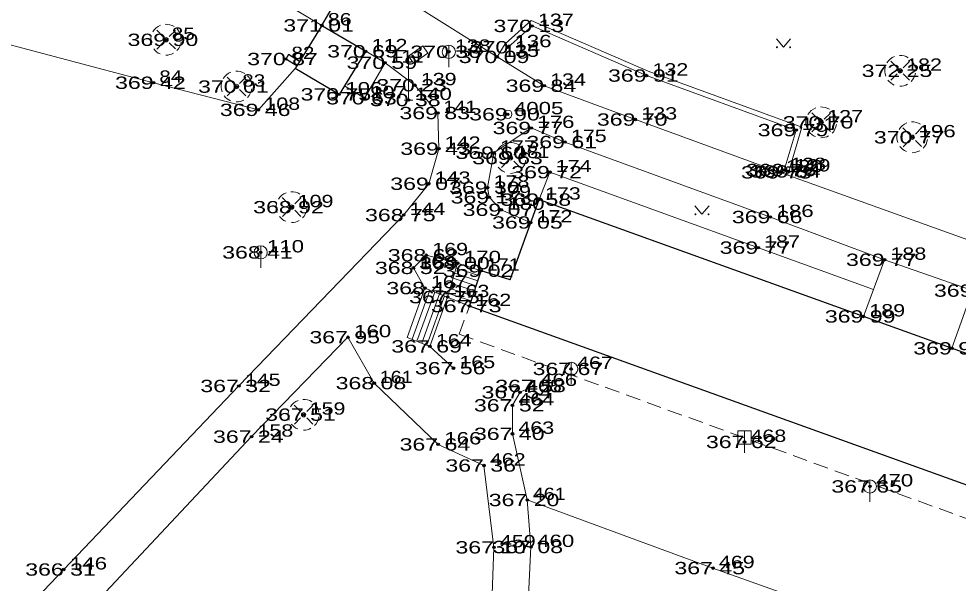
# Model space of a CAD drawing. Extents: x -789669 to -789458, y -977587 to -977420.
# Drawn here: x -789622.4 to -789569.1, y -977494.5 to -977462.4 of the extents above; entities that cross this region are included whole.
import ezdxf
from ezdxf.enums import TextEntityAlignment as Align

# ---------------------------------------------------------------- set-up
doc = ezdxf.new("R2010")
doc.units = 0
doc.header["$LTSCALE"] = 0.28
doc.header["$PDMODE"] = 32
doc.header["$PDSIZE"] = 0.14
doc.linetypes.add('MEDIUM_DASHED', pattern=[4.5, 3, -1.5])
for name, color, linetype, lineweight in [('1', 7, 'Continuous', 13), ('25', 7, 'Continuous', 13), ('3', 7, 'Continuous', 13), ('33', 7, 'Continuous', 13), ('4', 7, 'Continuous', 13), ('50', 7, 'Continuous', 13), ('9', 7, 'Continuous', 25)]:
    doc.layers.add(name, color=color, linetype=linetype, lineweight=lineweight)
for name, color, linetype in [('57', 7, 'Continuous'), ('58', 7, 'Continuous'), ('59', 7, 'Continuous')]:
    doc.layers.add(name, color=color, linetype=linetype)

msp = doc.modelspace()

# ---------------------------------------------------------------- linework, layer by layer
at = {"layer": '1'}
for p, q in [((-789595.27, -977464.56), (-789594.824, -977463.816)), ((-789602.74, -977464.24), (-789601.64, -977464.89)), ((-789601.64, -977464.89), (-789602.8, -977466.91)), ((-789603.949, -977466.202), (-789602.8, -977466.91)), ((-789578.805, -977471.28), (-789578.73, -977471.07)), ((-789597.52, -977476.28), (-789598.09, -977478.21)), ((-789597.52, -977476.28), (-789596.18, -977476.71)), ((-789573.29, -977476.09), (-789574.49, -977479.31)), ((-789597.69, -977476.855), (-789596.37, -977477.279)), ((-789597.605, -977476.568), (-789596.275, -977476.995)), ((-789597.86, -977477.432), (-789596.56, -977477.849)), ((-789597.775, -977477.143), (-789596.465, -977477.564)), ((-789600.39, -977480.5), (-789599.38, -977477.7)), ((-789600.111, -977480.61), (-789599.101, -977477.81)), ((-789599.832, -977480.721), (-789598.822, -977477.921)), ((-789597.945, -977477.719), (-789596.654, -977478.133)), ((-789568.3, -977477.84), (-789569.47, -977481.12)), ((-789599.552, -977480.831), (-789598.542, -977478.031)), ((-789599.273, -977480.941), (-789598.263, -977478.141)), ((-789598.03, -977478.007), (-789596.749, -977478.418)), ((-789599.1, -977481.01), (-789600.39, -977480.5))]:
    msp.add_line(p, q, dxfattribs=at)
for points in [[(-789605.23, -977462.77), (-789609.01, -977460.5), (-789610.31, -977459.07), (-789610.84, -977457.94), (-789611.05, -977457.83), (-789612.47, -977456.96), (-789628.38, -977447.2), (-789642.41, -977438.73)], [(-789600.83, -977460.98), (-789599.99, -977461.6), (-789595.27, -977464.56), (-789592.61, -977466.2), (-789587.43, -977468.12), (-789579.25, -977471.12)], [(-789601.64, -977464.89), (-789599.95, -977466.17), (-789598.64, -977467.75), (-789598.59, -977469.78), (-789599.16, -977471.77), (-789600.59, -977473.55), (-789609.94, -977483.26), (-789619.88, -977493.69), (-789629.88, -977504.18), (-789634.89, -977509.42), (-789637.37, -977512.43)], [(-789591.43, -977469.4), (-789593.35, -977468.6), (-789595.46, -977470.01), (-789595.82, -977471.99), (-789595.73, -977472.54), (-789595.05, -977473.25), (-789593.38, -977473.97)], [(-789591.43, -977469.4), (-789579.77, -977473.66), (-789573.29, -977476.09), (-789568.3, -977477.84), (-789563.66, -977479.48), (-789554.46, -977482.75), (-789542.34, -977487.22), (-789543.54, -977490.46)], [(-789592.9, -977472.67), (-789592.29, -977471.11), (-789573.917, -977477.772)], [(-789528.28, -977489.67), (-789537.88, -977485.96), (-789544.73, -977483.69), (-789553.55, -977480.4), (-789562.72, -977477.06), (-789579.25, -977471.12)], [(-789596.18, -977476.71), (-789597.52, -977476.28), (-789599.3, -977475.83), (-789600.03, -977476.55), (-789599.38, -977477.7), (-789598.09, -977478.21), (-789596.85, -977478.72)], [(-789597.76, -977482.25), (-789599.1, -977481.01), (-789598.09, -977478.21)], [(-789624.85, -977503.61), (-789625.01, -977502.71), (-789618.92, -977496.49), (-789609.22, -977486.14), (-789603.75, -977480.49), (-789602.26, -977483.1), (-789598.63, -977486.58)], [(-789593.53, -977495.98), (-789593.36, -977492.41), (-789593.57, -977489.74), (-789594.41, -977485.98), (-789594.41, -977484.36), (-789594.41, -977484.36), (-789593.98, -977483.62), (-789593.2, -977483.26)], [(-789598.63, -977486.58), (-789596.03, -977487.78), (-789595.46, -977492.43), (-789595.58, -977495.6), (-789596.49, -977499.86), (-789598.03, -977504.82)], [(-789555.4, -977503.56), (-789567.6, -977499.13), (-789583.03, -977493.61), (-789593.57, -977489.74)]]:
    msp.add_lwpolyline(points, dxfattribs=at)
at = {"layer": '25'}
for p, q in [((-789598.022, -977465.144), (-789598.022, -977463.895)), ((-789608.702, -977476.544), (-789608.702, -977475.295)), ((-789591.082, -977483.164), (-789591.082, -977481.915)), ((-789574.122, -977489.844), (-789574.122, -977488.595))]:
    msp.add_line(p, q, dxfattribs=at)
msp.add_lwpolyline([(-789581.24, -977487.065), (-789581.24, -977485.815), (-789580.865, -977485.815), (-789580.865, -977486.565), (-789581.615, -977486.565), (-789581.615, -977485.815), (-789581.24, -977485.815)], dxfattribs=at)
for centre in [(-789598.02, -977464.27), (-789608.7, -977475.67), (-789591.08, -977482.29), (-789574.12, -977488.97)]:
    msp.add_circle(centre, 0.375, dxfattribs=at)
at = {"layer": '3', "lineweight": 25}
msp.add_line((-789605.23, -977462.77), (-789603.31, -977459.5), dxfattribs=at)
at = {"layer": '3'}
for p, q in [((-789594.65, -977464.01), (-789594.824, -977463.816)), ((-789578.98, -977470.99), (-789578.73, -977471.07))]:
    msp.add_line(p, q, dxfattribs=at)
for points in [[(-789666.71, -977502.39), (-789654.87, -977463.01), (-789641.19, -977459.01), (-789614.78, -977466.03), (-789608.83, -977467.57), (-789606.74, -977465.22)], [(-789578.73, -977471.07), (-789577.981, -977468.56), (-789586.704, -977465.378), (-789593.349, -977462.495), (-789594.824, -977463.816)], [(-789578.98, -977470.99), (-789578.3, -977468.72), (-789586.8, -977465.62), (-789593.3, -977462.8), (-789594.65, -977464.01)]]:
    msp.add_lwpolyline(points, dxfattribs=at)
at = {"layer": '33'}
for p, q in [((-789600.31, -977464.51), (-789600.31, -977467.01)), ((-789600.56, -977467.01), (-789600.06, -977467.01))]:
    msp.add_line(p, q, dxfattribs=at)
msp.add_lwpolyline([(-789600.31, -977464.51), (-789599.49, -977463.937), (-789599.204, -977464.347), (-789600.024, -977464.92)], close=True, dxfattribs=at)
at = {"layer": '4'}
for p, q in [((-789614.604, -977463.046), (-789614.247, -977463.402)), ((-789614.07, -977463.59), (-789614.07, -977463.578)), ((-789613.544, -977463.054), (-789613.897, -977463.407)), ((-789614.6, -977464.117), (-789614.248, -977463.766)), ((-789613.896, -977463.761), (-789613.544, -977464.111)), ((-789572.934, -977464.812), (-789572.577, -977465.168)), ((-789571.874, -977464.82), (-789572.227, -977465.173)), ((-789610.604, -977465.706), (-789610.247, -977466.062)), ((-789609.544, -977465.714), (-789609.897, -977466.067)), ((-789572.93, -977465.883), (-789572.578, -977465.532)), ((-789572.4, -977465.356), (-789572.4, -977465.344)), ((-789572.226, -977465.527), (-789571.874, -977465.877)), ((-789610.07, -977466.25), (-789610.07, -977466.238)), ((-789610.6, -977466.777), (-789610.248, -977466.426)), ((-789609.896, -977466.421), (-789609.544, -977466.771)), ((-789577.414, -977467.742), (-789577.057, -977468.098)), ((-789576.354, -977467.75), (-789576.707, -977468.103)), ((-789576.88, -977468.286), (-789576.88, -977468.274)), ((-789577.41, -977468.813), (-789577.058, -977468.462)), ((-789576.706, -977468.457), (-789576.354, -977468.807)), ((-789572.244, -977468.592), (-789571.887, -977468.948)), ((-789571.184, -977468.6), (-789571.537, -977468.953)), ((-789572.24, -977469.663), (-789571.888, -977469.312)), ((-789571.71, -977469.136), (-789571.71, -977469.124)), ((-789571.536, -977469.307), (-789571.184, -977469.657)), ((-789595.044, -977469.766), (-789594.687, -977470.122)), ((-789593.984, -977469.774), (-789594.337, -977470.127)), ((-789595.04, -977470.837), (-789594.688, -977470.486)), ((-789594.51, -977470.31), (-789594.51, -977470.298)), ((-789594.336, -977470.481), (-789593.984, -977470.831)), ((-789607.474, -977472.556), (-789607.117, -977472.912)), ((-789606.414, -977472.564), (-789606.767, -977472.917)), ((-789606.94, -977473.1), (-789606.94, -977473.088)), ((-789607.47, -977473.627), (-789607.118, -977473.276)), ((-789606.766, -977473.271), (-789606.414, -977473.621)), ((-789606.794, -977484.358), (-789606.437, -977484.714)), ((-789605.734, -977484.366), (-789606.087, -977484.719)), ((-789606.26, -977484.902), (-789606.26, -977484.89)), ((-789606.79, -977485.429), (-789606.438, -977485.078)), ((-789606.086, -977485.073), (-789605.734, -977485.423))]:
    msp.add_line(p, q, dxfattribs=at)
for points in [[(-789579.423, -977463.534), (-789579.021, -977464.013), (-789578.619, -977463.534)], [(-789579.395, -977463.99), (-789579.381, -977463.998), (-789579.376, -977464.013), (-789579.382, -977464.026), (-789579.395, -977464.034), (-789579.411, -977464.026), (-789579.417, -977464.013), (-789579.413, -977463.999), (-789579.402, -977463.993), (-789579.387, -977463.999), (-789579.382, -977464.013), (-789579.385, -977464.023), (-789579.395, -977464.028), (-789579.406, -977464.023), (-789579.412, -977464.012), (-789579.407, -977464.002), (-789579.402, -977463.999), (-789579.391, -977464.003), (-789579.386, -977464.013), (-789579.392, -977464.02), (-789579.4, -977464.018), (-789579.405, -977464.01), (-789579.4, -977464.005), (-789579.392, -977464.009), (-789579.395, -977464.013)], [(-789578.645, -977463.991), (-789578.631, -977463.999), (-789578.626, -977464.014), (-789578.632, -977464.027), (-789578.645, -977464.035), (-789578.661, -977464.027), (-789578.667, -977464.014), (-789578.663, -977464), (-789578.652, -977463.994), (-789578.637, -977464), (-789578.632, -977464.014), (-789578.635, -977464.024), (-789578.645, -977464.029), (-789578.656, -977464.024), (-789578.662, -977464.013), (-789578.657, -977464.003), (-789578.652, -977464), (-789578.641, -977464.004), (-789578.636, -977464.014), (-789578.642, -977464.021), (-789578.65, -977464.019), (-789578.655, -977464.011), (-789578.65, -977464.006), (-789578.642, -977464.01), (-789578.645, -977464.014)], [(-789584.053, -977473.027), (-789583.651, -977473.506), (-789583.249, -977473.027)], [(-789584.025, -977473.483), (-789584.011, -977473.491), (-789584.006, -977473.506), (-789584.012, -977473.519), (-789584.025, -977473.527), (-789584.041, -977473.519), (-789584.047, -977473.506), (-789584.043, -977473.492), (-789584.032, -977473.486), (-789584.017, -977473.492), (-789584.012, -977473.506), (-789584.015, -977473.516), (-789584.025, -977473.521), (-789584.036, -977473.516), (-789584.042, -977473.505), (-789584.037, -977473.495), (-789584.032, -977473.492), (-789584.021, -977473.496), (-789584.016, -977473.506), (-789584.022, -977473.513), (-789584.03, -977473.511), (-789584.035, -977473.503), (-789584.03, -977473.498), (-789584.022, -977473.502), (-789584.025, -977473.506)], [(-789583.275, -977473.484), (-789583.261, -977473.492), (-789583.256, -977473.507), (-789583.262, -977473.52), (-789583.275, -977473.528), (-789583.291, -977473.52), (-789583.297, -977473.507), (-789583.293, -977473.493), (-789583.282, -977473.487), (-789583.267, -977473.493), (-789583.262, -977473.507), (-789583.265, -977473.517), (-789583.275, -977473.522), (-789583.286, -977473.517), (-789583.292, -977473.506), (-789583.287, -977473.496), (-789583.282, -977473.493), (-789583.271, -977473.497), (-789583.266, -977473.507), (-789583.272, -977473.514), (-789583.28, -977473.512), (-789583.285, -977473.504), (-789583.28, -977473.499), (-789583.272, -977473.503), (-789583.275, -977473.507)]]:
    msp.add_lwpolyline(points, dxfattribs=at)
for centre, radius in [((-789614.0739, -977463.5834), 0.125), ((-789579.396, -977464.013), 0.025), ((-789578.646, -977464.013), 0.025), ((-789572.4039, -977465.3494), 0.125), ((-789610.0739, -977466.2434), 0.125), ((-789576.8839, -977468.2794), 0.125), ((-789571.7139, -977469.1294), 0.125), ((-789594.5139, -977470.3034), 0.125), ((-789606.9439, -977473.0934), 0.125), ((-789584.0262, -977473.5057), 0.025), ((-789583.2762, -977473.5057), 0.025), ((-789606.2639, -977484.8954), 0.125)]:
    msp.add_circle(centre, radius, dxfattribs=at)
for centre, start, end in [((-789614.0739, -977463.5834), 111.04924, 149.34666), ((-789614.0739, -977463.5834), 57.94289, 92.85253), ((-789614.0739, -977463.5834), 9.68453, 44.47714), ((-789614.0739, -977463.5834), 166.76695, 200.11735), ((-789614.0739, -977463.5834), 217.06959, 247.69959), ((-789614.0739, -977463.5834), 315.09105, 351.67435), ((-789614.0739, -977463.5834), 269.18965, 298.56841), ((-789572.4039, -977465.3494), 111.04924, 149.34666), ((-789572.4039, -977465.3494), 57.94289, 92.85253), ((-789572.4039, -977465.3494), 166.76695, 200.11735), ((-789572.4039, -977465.3494), 9.68453, 44.47714), ((-789610.0739, -977466.2434), 111.04924, 149.34666), ((-789610.0739, -977466.2434), 57.94289, 92.85253), ((-789610.0739, -977466.2434), 9.68453, 44.47714), ((-789572.4039, -977465.3494), 315.09105, 351.67435), ((-789610.0739, -977466.2434), 166.76695, 200.11735), ((-789572.4039, -977465.3494), 217.06959, 247.69959), ((-789572.4039, -977465.3494), 269.18965, 298.56841), ((-789610.0739, -977466.2434), 217.06959, 247.69959), ((-789610.0739, -977466.2434), 315.09105, 351.67435), ((-789610.0739, -977466.2434), 269.18965, 298.56841), ((-789576.8839, -977468.2794), 111.04924, 149.34666), ((-789576.8839, -977468.2794), 57.94289, 92.85253), ((-789576.8839, -977468.2794), 9.68453, 44.47714), ((-789576.8839, -977468.2794), 166.76695, 200.11735), ((-789571.7139, -977469.1294), 111.04924, 149.34666), ((-789571.7139, -977469.1294), 57.94289, 92.85253), ((-789576.8839, -977468.2794), 217.06959, 247.69959), ((-789576.8839, -977468.2794), 315.09105, 351.67435), ((-789571.7139, -977469.1294), 9.68453, 44.47714), ((-789594.5139, -977470.3034), 57.94289, 92.85253), ((-789576.8839, -977468.2794), 269.18965, 298.56841), ((-789571.7139, -977469.1294), 166.76695, 200.11735), ((-789571.7139, -977469.1294), 315.09105, 351.67435), ((-789594.5139, -977470.3034), 111.04924, 149.34666), ((-789594.5139, -977470.3034), 9.68453, 44.47714), ((-789571.7139, -977469.1294), 217.06959, 247.69959), ((-789571.7139, -977469.1294), 269.18965, 298.56841), ((-789594.5139, -977470.3034), 166.76695, 200.11735), ((-789594.5139, -977470.3034), 315.09105, 351.67435), ((-789594.5139, -977470.3034), 217.06959, 247.69959), ((-789594.5139, -977470.3034), 269.18965, 298.56841), ((-789606.9439, -977473.0934), 111.04924, 149.34666), ((-789606.9439, -977473.0934), 57.94289, 92.85253), ((-789606.9439, -977473.0934), 9.68453, 44.47714), ((-789606.9439, -977473.0934), 166.76695, 200.11735), ((-789606.9439, -977473.0934), 217.06959, 247.69959), ((-789606.9439, -977473.0934), 315.09105, 351.67435), ((-789606.9439, -977473.0934), 269.18965, 298.56841), ((-789606.2639, -977484.8954), 111.04924, 149.34666), ((-789606.2639, -977484.8954), 57.94289, 92.85253), ((-789606.2639, -977484.8954), 9.68453, 44.47714), ((-789606.2639, -977484.8954), 166.76695, 200.11735), ((-789606.2639, -977484.8954), 217.06959, 247.69959), ((-789606.2639, -977484.8954), 315.09105, 351.67435), ((-789606.2639, -977484.8954), 269.18965, 298.56841)]:
    msp.add_arc(centre, 0.875, start, end, dxfattribs=at)
at = {"layer": '50'}
msp.add_line((-789594.688, -977467.82), (-789594.672, -977467.82), dxfattribs=at)
msp.add_circle((-789594.6798, -977467.8205), 0.24, dxfattribs=at)
at = {"layer": '57'}
for p in [(-789605.23, -977462.77), (-789593.3, -977462.8), (-789614.07, -977463.59), (-789594.65, -977464.01), (-789607.28, -977464.68), (-789602.74, -977464.24), (-789598.02, -977464.27), (-789595.27, -977464.56), (-789601.64, -977464.89), (-789586.8, -977465.62), (-789572.4, -977465.35), (-789614.78, -977466.03), (-789610.07, -977466.25), (-789599.95, -977466.17), (-789592.61, -977466.2), (-789604.25, -977466.69), (-789602.8, -977466.91), (-789600.31, -977467.01), (-789608.83, -977467.57), (-789598.64, -977467.75), (-789594.68, -977467.82), (-789587.43, -977468.12), (-789576.88, -977468.28), (-789593.35, -977468.6), (-789578.3, -977468.72), (-789591.43, -977469.4), (-789571.71, -977469.13), (-789598.59, -977469.78), (-789595.46, -977470.01), (-789594.51, -977470.31), (-789592.29, -977471.11), (-789579.25, -977471.12), (-789578.98, -977470.99), (-789578.73, -977471.07), (-789599.16, -977471.77), (-789595.82, -977471.99), (-789595.73, -977472.54), (-789592.9, -977472.67), (-789606.94, -977473.1), (-789595.05, -977473.25), (-789600.59, -977473.55), (-789579.77, -977473.66), (-789593.38, -977473.97), (-789608.7, -977475.67), (-789599.3, -977475.83), (-789580.46, -977475.4), (-789597.52, -977476.28), (-789573.29, -977476.09), (-789600.03, -977476.55), (-789596.18, -977476.71), (-789599.38, -977477.7), (-789598.09, -977478.21), (-789596.85, -977478.72), (-789574.49, -977479.31), (-789603.75, -977480.49), (-789599.1, -977481.01), (-789569.47, -977481.12), (-789597.76, -977482.25), (-789591.08, -977482.29), (-789609.94, -977483.26), (-789602.26, -977483.1), (-789593.2, -977483.26), (-789593.98, -977483.62), (-789594.41, -977484.36), (-789606.26, -977484.89), (-789594.41, -977485.98), (-789609.22, -977486.14), (-789598.63, -977486.58), (-789581.24, -977486.44), (-789596.03, -977487.78), (-789574.12, -977488.97), (-789593.57, -977489.74), (-789595.46, -977492.43), (-789593.36, -977492.41), (-789619.88, -977493.69), (-789583.03, -977493.61)]:
    msp.add_point(p, dxfattribs=at)
at = {"layer": '9'}
for p, q in [((-789605.23, -977462.77), (-789606.74, -977465.22)), ((-789607.123, -977464.425), (-789607.28, -977464.68)), ((-789606.49, -977464.815), (-789607.123, -977464.425)), ((-789606.647, -977465.07), (-789607.28, -977464.68)), ((-789604.25, -977466.69), (-789606.74, -977465.22)), ((-789594.546, -977477.235), (-789592.9, -977472.67)), ((-789592.9, -977472.67), (-789543.54, -977490.46)), ((-789596.85, -977478.72), (-789596.18, -977476.71)), ((-789594.546, -977477.235), (-789596.18, -977476.71)), ((-789546.04, -977497.05), (-789596.85, -977478.72))]:
    msp.add_line(p, q, dxfattribs=at)
at = {"layer": '9', "linetype": 'MEDIUM_DASHED', "lineweight": 13}
for q in [(-789596.85, -977478.72), (-789543.101, -977500.084)]:
    msp.add_line((-789597.427, -977480.319), q, dxfattribs=at)
at = {"layer": '9'}
msp.add_lwpolyline([(-789605.23, -977462.77), (-789602.74, -977464.24), (-789604.25, -977466.69)], dxfattribs=at)

# ---------------------------------------------------------------- texts
at = {"layer": '50', "width": 1.35}
msp.add_text(' 4005', height=0.7, dxfattribs=at).set_placement((-789594.68, -977467.82))
at = {"layer": '58'}
for s, width, p in [(' 86', 1.3, (-789605.23, -977462.77)), (' 137', 1.3, (-789593.3, -977462.8)), (' 85', 1.25, (-789614.07, -977463.59)), (' 112', 1.3, (-789602.74, -977464.24)), (' 138', 1.3, (-789598.02, -977464.27)), (' 136', 1.35, (-789594.65, -977464.01)), (' 82', 1.25, (-789607.28, -977464.68)), (' 135', 1.3, (-789595.27, -977464.56)), (' 111', 1.2, (-789601.64, -977464.89)), (' 182', 1.3, (-789572.4, -977465.35)), (' 132', 1.3, (-789586.8, -977465.62)), (' 84', 1.25, (-789614.78, -977466.03)), (' 83', 1.25, (-789610.07, -977466.25)), (' 139', 1.3, (-789599.95, -977466.17)), (' 134', 1.3, (-789592.61, -977466.2)), (' 106', 1.35, (-789604.25, -977466.69)), (' 107', 1.3, (-789602.8, -977466.91)), (' 140', 1.35, (-789600.31, -977467.01)), (' 108', 1.3, (-789608.83, -977467.57)), (' 141', 1.2, (-789598.64, -977467.75)), (' 4005', 1.35, (-789594.68, -977467.82)), (' 133', 1.3, (-789587.43, -977468.12)), (' 127', 1.3, (-789576.88, -977468.28)), (' 176', 1.35, (-789593.35, -977468.6)), (' 131', 1.2, (-789578.3, -977468.72)), (' 175', 1.3, (-789591.43, -977469.4)), (' 196', 1.35, (-789571.71, -977469.13)), (' 142', 1.3, (-789598.59, -977469.78)), (' 177', 1.3, (-789595.46, -977470.01)), (' 181', 1.2, (-789594.51, -977470.31)), (' 174', 1.3, (-789592.29, -977471.11)), (' 130', 1.35, (-789579.25, -977471.12)), (' 128', 1.3, (-789578.98, -977470.99)), (' 129', 1.3, (-789578.73, -977471.07)), (' 143', 1.3, (-789599.16, -977471.77)), (' 178', 1.3, (-789595.82, -977471.99)), (' 179', 1.3, (-789595.73, -977472.54)), (' 173', 1.3, (-789592.9, -977472.67)), (' 109', 1.3, (-789606.94, -977473.1)), (' 180', 1.35, (-789595.05, -977473.25)), (' 144', 1.3, (-789600.59, -977473.55)), (' 186', 1.35, (-789579.77, -977473.66)), (' 172', 1.3, (-789593.38, -977473.97)), (' 187', 1.3, (-789580.46, -977475.4)), (' 110', 1.35, (-789608.7, -977475.67)), (' 169', 1.3, (-789599.3, -977475.83)), (' 168', 1.3, (-789600.03, -977476.55)), (' 170', 1.35, (-789597.52, -977476.28)), (' 188', 1.3, (-789573.29, -977476.09)), (' 171', 1.2, (-789596.18, -977476.71)), (' 167', 1.3, (-789599.38, -977477.7)), (' 163', 1.3, (-789598.09, -977478.21)), (' 162', 1.3, (-789596.85, -977478.72)), (' 189', 1.3, (-789574.49, -977479.31)), (' 160', 1.35, (-789603.75, -977480.49)), (' 164', 1.3, (-789599.1, -977481.01)), (' 165', 1.3, (-789597.76, -977482.25)), (' 467', 1.3, (-789591.08, -977482.29)), (' 145', 1.3, (-789609.94, -977483.26)), (' 161', 1.2, (-789602.26, -977483.1)), (' 466', 1.35, (-789593.2, -977483.26)), (' 465', 1.3, (-789593.98, -977483.62)), (' 464', 1.3, (-789594.41, -977484.36)), (' 159', 1.3, (-789606.26, -977484.89)), (' 158', 1.3, (-789609.22, -977486.14)), (' 463', 1.3, (-789594.41, -977485.98)), (' 166', 1.35, (-789598.63, -977486.58)), (' 468', 1.3, (-789581.24, -977486.44)), (' 462', 1.3, (-789596.03, -977487.78)), (' 470', 1.35, (-789574.12, -977488.97)), (' 461', 1.2, (-789593.57, -977489.74)), (' 459', 1.3, (-789595.46, -977492.43)), (' 460', 1.35, (-789593.36, -977492.41)), (' 469', 1.3, (-789583.03, -977493.61)), (' 146', 1.35, (-789619.88, -977493.69))]:
    msp.add_text(s, height=0.7, dxfattribs=dict(at, width=width)).set_placement(p)
at = {"layer": '59', "width": 1.4}
for s, p in [('371 01 ', (-789605.23, -977463.12)), ('370 13 ', (-789593.3, -977463.15)), ('369 90 ', (-789614.07, -977463.94)), ('370 69 ', (-789602.74, -977464.59)), ('370 36 ', (-789598.02, -977464.62)), ('370 14 ', (-789594.65, -977464.36)), ('370 87 ', (-789607.28, -977465.03)), ('370 59 ', (-789601.64, -977465.24)), ('370 09 ', (-789595.27, -977464.91)), ('372 25 ', (-789572.4, -977465.7)), ('369 42 ', (-789614.78, -977466.38)), ('369 91 ', (-789586.8, -977465.97)), ('370 01 ', (-789610.07, -977466.6)), ('370 23 ', (-789599.95, -977466.52)), ('369 84 ', (-789592.61, -977466.55)), ('370 75 ', (-789604.25, -977467.04)), ('370 63 ', (-789602.8, -977467.26)), ('370 38 ', (-789600.31, -977467.36)), ('369 46 ', (-789608.83, -977467.92)), ('369 83 ', (-789598.64, -977468.1)), ('369 90 ', (-789594.68, -977468.17)), ('369 70 ', (-789587.43, -977468.47)), ('369 77 ', (-789593.35, -977468.95)), ('369 79 ', (-789578.3, -977469.07)), ('370 70 ', (-789576.88, -977468.63)), ('370 77 ', (-789571.71, -977469.48)), ('369 43 ', (-789598.59, -977470.13)), ('369 61 ', (-789591.43, -977469.75)), ('369 60 ', (-789595.46, -977470.36)), ('369 63 ', (-789594.51, -977470.66)), ('369 72 ', (-789592.29, -977471.46)), ('369 73 ', (-789579.25, -977471.47)), ('369 76 ', (-789578.98, -977471.34)), ('369 84 ', (-789578.73, -977471.42)), ('369 07 ', (-789599.16, -977472.12)), ('369 30 ', (-789595.82, -977472.34)), ('369 17 ', (-789595.73, -977472.89)), ('369 58 ', (-789592.9, -977473.02)), ('368 92 ', (-789606.94, -977473.45)), ('369 07 ', (-789595.05, -977473.6)), ('368 75 ', (-789600.59, -977473.9)), ('369 05 ', (-789593.38, -977474.32)), ('369 66 ', (-789579.77, -977474.01)), ('368 41 ', (-789608.7, -977476.02)), ('369 77 ', (-789580.46, -977475.75)), ('368 62 ', (-789599.3, -977476.18)), ('369 77 ', (-789573.29, -977476.44)), ('368 52 ', (-789600.03, -977476.9)), ('369 00 ', (-789597.52, -977476.63)), ('369 02 ', (-789596.18, -977477.06)), ('368 42 ', (-789599.38, -977478.05)), ('367 75 ', (-789598.09, -977478.56)), ('369 90 ', (-789568.3, -977478.19)), ('367 73 ', (-789596.85, -977479.07)), ('369 99 ', (-789574.49, -977479.66)), ('367 95 ', (-789603.75, -977480.84)), ('367 69 ', (-789599.1, -977481.36)), ('369 99 ', (-789569.47, -977481.47)), ('367 56 ', (-789597.76, -977482.6)), ('367 67 ', (-789591.08, -977482.64)), ('368 08 ', (-789602.26, -977483.45)), ('367 32 ', (-789609.94, -977483.61)), ('367 54 ', (-789593.98, -977483.97)), ('367 58 ', (-789593.2, -977483.61)), ('367 52 ', (-789594.41, -977484.71)), ('367 51 ', (-789606.26, -977485.24)), ('367 24 ', (-789609.22, -977486.49)), ('367 40 ', (-789594.41, -977486.33)), ('367 64 ', (-789598.63, -977486.93)), ('367 62 ', (-789581.24, -977486.79)), ('367 36 ', (-789596.03, -977488.13)), ('367 65 ', (-789574.12, -977489.32)), ('367 20 ', (-789593.57, -977490.09)), ('367 10 ', (-789595.46, -977492.78)), ('367 08 ', (-789593.36, -977492.76)), ('366 31 ', (-789619.88, -977494.04)), ('367 45 ', (-789583.03, -977493.96))]:
    msp.add_text(s, height=0.7, dxfattribs=at).set_placement(p, align=Align.CENTER)

doc.saveas('drawing.dxf')
